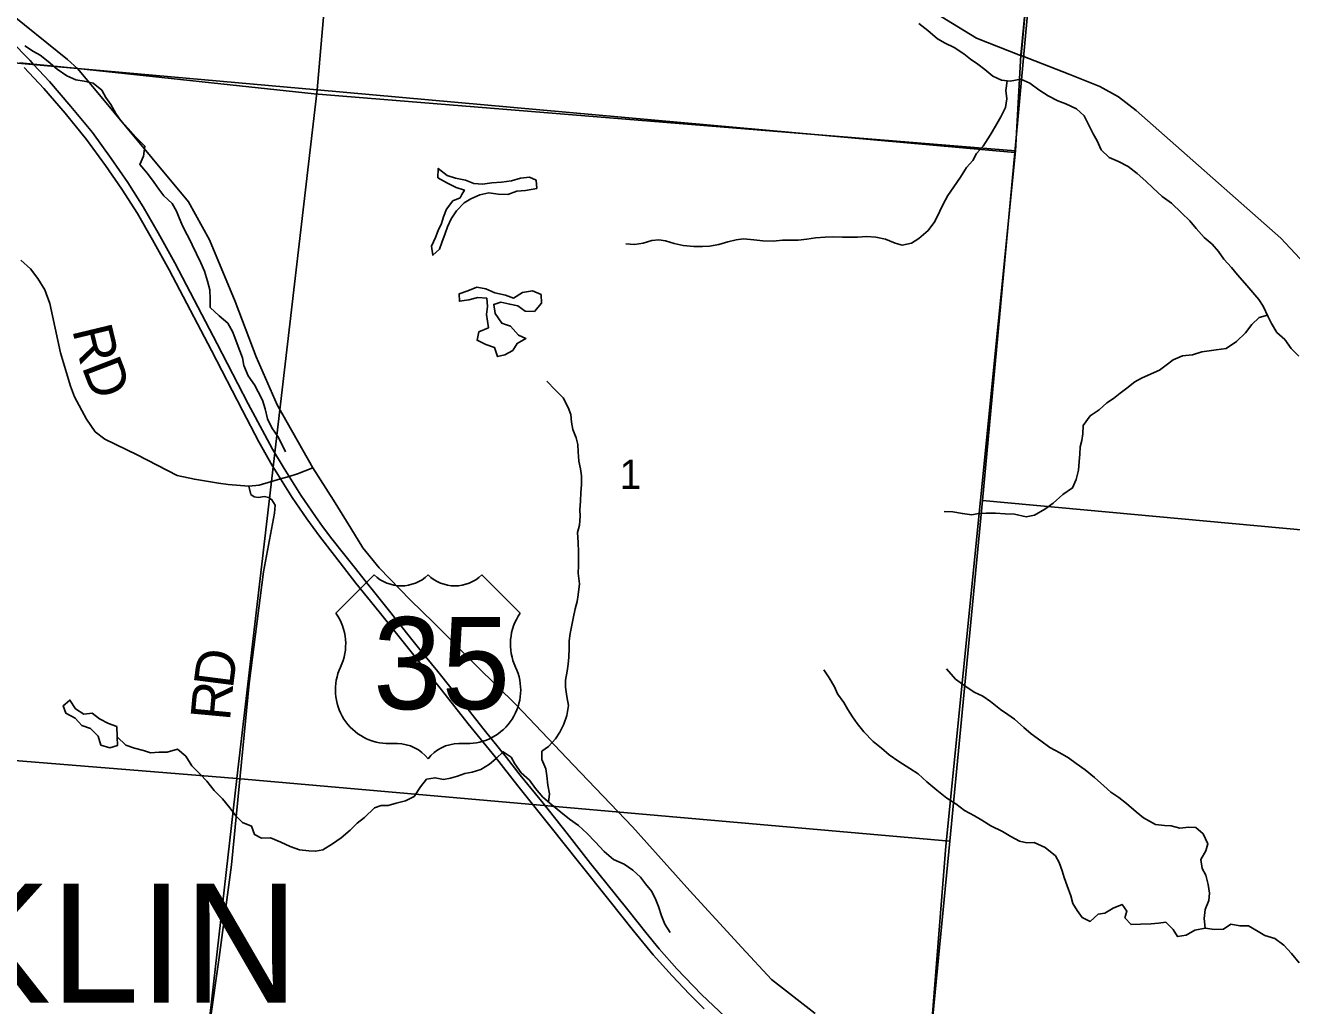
# Model space of a CAD drawing. Extents: x 0 to 42, y 0 to 22.
# Drawn here: x 4.613 to 5.519, y 18.932 to 19.634 of the extents above; entities that cross this region are included whole.
import ezdxf

# ---------------------------------------------------------------- set-up
doc = ezdxf.new("R2010")
doc.units = 0
for name, color, linetype in [('GM_X_County_Road', 7, 'Continuous'), ('GM_X_County_Road_Text', 7, 'Continuous'), ('GM_X_Minor_Lake', 7, 'Continuous'), ('GM_X_Minor_River', 7, 'Continuous'), ('GM_X_Section', 7, 'Continuous'), ('GM_X_Section_Text', 7, 'Continuous'), ('GM_X_Township', 7, 'Continuous'), ('GM_X_Township_Road', 7, 'Continuous'), ('GM_X_Township_Road_Text', 7, 'Continuous'), ('GM_X_Township_Text', 7, 'Continuous'), ('GM_X_US_Location', 7, 'Continuous'), ('GM_X_US_Route', 7, 'Continuous'), ('GM_X_US_Shield', 7, 'Continuous')]:
    doc.layers.add(name, color=color, linetype=linetype)

msp = doc.modelspace()

# ---------------------------------------------------------------- linework, layer by layer
at = {"layer": 'GM_X_County_Road'}
for points in [[(4.56999, 19.90283), (4.62719, 19.905), (4.65123, 19.90408), (4.71319, 19.89287), (4.78901, 19.87893), (4.84181, 19.86545), (4.89019, 19.84005), (4.95082, 19.79872), (4.99136, 19.77157), (5.00597, 19.76108), (5.01352, 19.75892), (5.02324, 19.75676), (5.04483, 19.75461), (5.06318, 19.75461), (5.07721, 19.75137), (5.09016, 19.74814), (5.10635, 19.74058), (5.13071, 19.7321), (5.18067, 19.69826), (5.21435, 19.67373), (5.29367, 19.62493), (5.32517, 19.61272)], [(4.59734, 19.64654), (4.64306, 19.60986), (4.65044, 19.60313), (4.72963, 19.50788), (4.7446, 19.48056), (4.76309, 19.43651), (4.77807, 19.39686), (4.79303, 19.3625), (4.81848, 19.31743), (4.83337, 19.29427), (4.84568, 19.27418), (4.85426, 19.26009), (4.86608, 19.24568), (4.88842, 19.22268), (4.90493, 19.20649), (4.93634, 19.17507), (4.96415, 19.14754), (5.00529, 19.10436), (5.04743, 19.06016), (5.08856, 19.01444), (5.12563, 18.9738), (5.14696, 18.95094), (5.17825, 18.92667)], [(5.32517, 19.61272), (5.32564, 19.61254), (5.36052, 19.59906), (5.38208, 19.59043), (5.39538, 19.58306), (5.40796, 19.57318), (5.51147, 19.48189), (5.55598, 19.43435), (5.59644, 19.39927), (5.61778, 19.3761), (5.63493, 19.35748), (5.63974, 19.35428), (5.64703, 19.35096), (5.6616, 19.345), (5.67378, 19.34602), (5.70224, 19.33874), (5.7982, 19.31027), (5.82798, 19.30233), (5.84783, 19.30034), (5.90342, 19.3063), (5.99019, 19.31629), (6.04688, 19.31444), (6.10243, 19.31289)], [(4.60949, 19.46598), (4.61651, 19.45974), (4.62181, 19.45303), (4.6268, 19.44492), (4.63024, 19.4351), (4.638, 19.39961), (4.64505, 19.37587), (4.64787, 19.36811), (4.65656, 19.35213), (4.66267, 19.34319), (4.66972, 19.33779), (4.69274, 19.32674), (4.72141, 19.31193), (4.73386, 19.30911), (4.75114, 19.30642)], [(4.75114, 19.30642), (4.75806, 19.30535), (4.77267, 19.30415), (4.78027, 19.30496), (4.79547, 19.30952), (4.80158, 19.31124), (4.80769, 19.31296), (4.81848, 19.31743)]]:
    msp.add_lwpolyline(points, dxfattribs=at)
at = {"layer": 'GM_X_Minor_Lake'}
for points in [[(4.97888, 19.51727), (4.97853, 19.52333), (4.97361, 19.52544), (4.96718, 19.52489), (4.96074, 19.52282), (4.95373, 19.5219), (4.94673, 19.52135), (4.94011, 19.52042), (4.93387, 19.52101), (4.92782, 19.52331), (4.92063, 19.52485), (4.91478, 19.52676), (4.90836, 19.53171), (4.90815, 19.52508), (4.91495, 19.52126), (4.92118, 19.51821), (4.92704, 19.51629), (4.92529, 19.51314)], [(4.92529, 19.51314), (4.92399, 19.5108), (4.91888, 19.50855), (4.91431, 19.50268), (4.91203, 19.49719), (4.91068, 19.49227), (4.90821, 19.48734), (4.9063, 19.48223), (4.90344, 19.47598), (4.90455, 19.46953), (4.9093, 19.47388), (4.91083, 19.4788), (4.91331, 19.48505), (4.91503, 19.48998), (4.91751, 19.49566), (4.92131, 19.50133), (4.92701, 19.507), (4.93175, 19.51002), (4.93819, 19.51284), (4.94463, 19.51434), (4.95125, 19.51337), (4.95806, 19.51297), (4.96469, 19.51541), (4.97093, 19.51596), (4.97888, 19.51727)], [(4.9564, 19.42008), (4.95377, 19.42102), (4.94906, 19.42786), (4.94814, 19.43431), (4.95306, 19.436), (4.95949, 19.43447), (4.96535, 19.43331), (4.97064, 19.4295), (4.97726, 19.42929), (4.9822, 19.43534), (4.98203, 19.44141), (4.9758, 19.44408), (4.96879, 19.44278), (4.96234, 19.43882), (4.95649, 19.44092), (4.94892, 19.44265), (4.94231, 19.44552), (4.93607, 19.44668), (4.92963, 19.44404), (4.92338, 19.44198), (4.92355, 19.43667), (4.93017, 19.43759), (4.93661, 19.43928), (4.94304, 19.43888), (4.94359, 19.43281), (4.94301, 19.42712), (4.9443, 19.41764)], [(4.9443, 19.41764), (4.93748, 19.41482), (4.93613, 19.40875), (4.94236, 19.4057), (4.9486, 19.40359), (4.95085, 19.39695), (4.95596, 19.39826), (4.96184, 19.40146), (4.96488, 19.40639), (4.97114, 19.40997), (4.96585, 19.41245), (4.96019, 19.41873), (4.9564, 19.42008)], [(4.64134, 19.1482), (4.63987, 19.14691), (4.64175, 19.1416), (4.64855, 19.13797), (4.65326, 19.13284), (4.6595, 19.13073), (4.66496, 19.12521), (4.66683, 19.11876), (4.67326, 19.11684), (4.67876, 19.11853), (4.67859, 19.12479)], [(4.67859, 19.12479), (4.67823, 19.132), (4.67238, 19.13429), (4.66576, 19.13754), (4.66067, 19.14173), (4.65461, 19.14099), (4.64857, 19.1448), (4.64462, 19.15107), (4.64134, 19.1482)]]:
    msp.add_lwpolyline(points, dxfattribs=at)
at = {"layer": 'GM_X_Minor_River'}
for points in [[(5.52433, 19.39739), (5.51887, 19.40291), (5.51435, 19.40918), (5.50869, 19.41432), (5.50492, 19.42078), (5.50248, 19.42553), (5.49891, 19.43312), (5.4959, 19.43787), (5.49157, 19.443), (5.48572, 19.44966), (5.48063, 19.45555), (5.4763, 19.46088), (5.47064, 19.46677), (5.46688, 19.47229), (5.46236, 19.47742), (5.4567, 19.48237), (5.45104, 19.48883), (5.44652, 19.49416), (5.44048, 19.50005), (5.43332, 19.5069), (5.42671, 19.51167), (5.41992, 19.51794), (5.41483, 19.5227), (5.40879, 19.52803), (5.40238, 19.53317), (5.39539, 19.5368), (5.38878, 19.53947), (5.38293, 19.54499), (5.38011, 19.55144), (5.3771, 19.55657), (5.37071, 19.56949), (5.36525, 19.57444), (5.35769, 19.57806), (5.35202, 19.58017), (5.34503, 19.58379), (5.33842, 19.58798), (5.33182, 19.59274), (5.32539, 19.59561), (5.31782, 19.59431), (5.31158, 19.5949), (5.30535, 19.59776), (5.29969, 19.60252), (5.29459, 19.60633), (5.2895, 19.60994), (5.28459, 19.61375), (5.27779, 19.61833), (5.27137, 19.62138), (5.26571, 19.62462), (5.25891, 19.63052), (5.25231, 19.63547)], [(4.61235, 19.61953), (4.61858, 19.61553), (4.62349, 19.61286), (4.62915, 19.60829), (4.63557, 19.60277), (4.64255, 19.598), (4.64897, 19.59514), (4.65484, 19.59417), (4.66127, 19.59282), (4.66749, 19.58768), (4.6705, 19.58255), (4.67389, 19.57761), (4.67746, 19.57115), (4.68085, 19.5664), (4.68632, 19.56031), (4.69179, 19.55404), (4.6982, 19.54776), (4.69742, 19.54056), (4.69475, 19.5345), (4.70021, 19.52822), (4.70492, 19.52157), (4.70831, 19.51682), (4.71189, 19.51207), (4.71793, 19.50674), (4.72094, 19.50123), (4.723, 19.49648), (4.72488, 19.49173)], [(5.31557, 19.59452), (5.31458, 19.58749), (5.31551, 19.58161), (5.31435, 19.57536), (5.31111, 19.56873), (5.3073, 19.56192), (5.3035, 19.55548), (5.29836, 19.54773), (5.2938, 19.54243), (5.29095, 19.53732), (5.28658, 19.5324), (5.2822, 19.52559), (5.27745, 19.51859), (5.27308, 19.51235), (5.26984, 19.5061), (5.26755, 19.50118), (5.26374, 19.4938), (5.25899, 19.48718), (5.25235, 19.48151), (5.24704, 19.4783), (5.24041, 19.47681), (5.2355, 19.47815), (5.22851, 19.48102), (5.22151, 19.48255), (5.21508, 19.48295), (5.20846, 19.48241), (5.20297, 19.48242), (5.19767, 19.48263), (5.19105, 19.48265), (5.18537, 19.48248), (5.17837, 19.48193), (5.17231, 19.48119), (5.16607, 19.48045), (5.15982, 19.48047), (5.1549, 19.4803), (5.14809, 19.47975), (5.14071, 19.47978), (5.13428, 19.48055), (5.12691, 19.48134), (5.1216, 19.4806), (5.11573, 19.4791), (5.10911, 19.47722), (5.10248, 19.47611), (5.09756, 19.47593), (5.09132, 19.47576), (5.08375, 19.47654), (5.07732, 19.47808), (5.07109, 19.47981), (5.06617, 19.48058), (5.06125, 19.48022), (5.055, 19.47815), (5.04875, 19.47722), (5.0427, 19.47781)], [(4.72488, 19.49173), (4.72713, 19.4868), (4.72995, 19.48167), (4.7322, 19.47692), (4.73521, 19.47065), (4.73841, 19.4642), (4.74103, 19.45812), (4.74328, 19.4511), (4.74477, 19.44483), (4.74513, 19.4382), (4.74511, 19.43213), (4.75152, 19.42623), (4.75775, 19.4209), (4.76132, 19.41444), (4.76376, 19.40798), (4.76638, 19.40115), (4.76826, 19.39602), (4.76918, 19.39052), (4.77219, 19.38331), (4.77671, 19.37666), (4.77934, 19.37172), (4.78254, 19.36583), (4.78441, 19.35957), (4.78608, 19.35235), (4.78928, 19.34609), (4.79342, 19.33982), (4.79605, 19.33488), (4.79906, 19.3288)], [(5.50195, 19.42665), (5.49605, 19.42498), (5.49073, 19.42007), (5.48617, 19.41401), (5.4799, 19.40778), (5.47251, 19.40287), (5.46531, 19.40176), (5.4602, 19.4012), (5.4549, 19.40046), (5.44827, 19.39821), (5.44127, 19.39747), (5.43445, 19.39465), (5.42951, 19.39087), (5.42477, 19.38729), (5.41871, 19.38465), (5.4117, 19.38164), (5.40696, 19.379), (5.40126, 19.37428), (5.39652, 19.37088), (5.39178, 19.36692), (5.38704, 19.3639), (5.38153, 19.35899), (5.37509, 19.35446), (5.36995, 19.34765), (5.36993, 19.34177), (5.36916, 19.33703), (5.36801, 19.33229), (5.36761, 19.32718), (5.36721, 19.32187), (5.36662, 19.31561), (5.36509, 19.30898), (5.36242, 19.30292), (5.35559, 19.2982), (5.34857, 19.29197), (5.3425, 19.28763), (5.3353, 19.28348), (5.32924, 19.28236), (5.32092, 19.28409), (5.3143, 19.2843), (5.3073, 19.2849), (5.30068, 19.28492), (5.29519, 19.28456), (5.29027, 19.28362), (5.28365, 19.28459), (5.27684, 19.28575), (5.2706, 19.28596)], [(4.9874, 19.07795), (4.988, 19.08378), (4.98688, 19.09004), (4.98615, 19.09668), (4.98541, 19.1018), (4.98259, 19.10844), (4.98261, 19.11432), (4.98735, 19.11772), (4.99229, 19.1232), (4.99534, 19.12812), (4.99819, 19.1338), (5.00049, 19.14005), (5.00165, 19.14706), (5.00053, 19.15351), (4.99942, 19.16034), (4.99944, 19.16527), (5.00059, 19.17172), (5.00137, 19.17664), (5.00176, 19.18176), (5.00216, 19.18821), (5.00218, 19.19333), (5.00277, 19.19864), (5.00392, 19.2047), (5.00489, 19.20944), (5.00642, 19.21626), (5.00777, 19.22156), (5.00854, 19.22649), (5.00951, 19.23426), (5.00859, 19.24185), (5.0088, 19.24716), (5.00882, 19.25209), (5.00883, 19.25721), (5.00848, 19.26385), (5.00812, 19.27105), (5.00947, 19.27617), (5.01006, 19.28261), (5.00969, 19.28735), (5.01009, 19.29342), (5.01049, 19.29968), (5.01089, 19.30517), (5.01091, 19.31162), (5.01017, 19.31674), (5.00906, 19.32206), (5.00851, 19.32888), (5.00834, 19.334), (5.00703, 19.33875), (5.00478, 19.34482), (5.00385, 19.34995), (5.00331, 19.35564), (5.00143, 19.36057), (4.99767, 19.36741), (4.99201, 19.37331), (4.98598, 19.37939)], [(5.20482, 19.13903), (5.20162, 19.14416), (5.19861, 19.14929), (5.19428, 19.15556), (5.19202, 19.1605), (5.18826, 19.16696), (5.1845, 19.17266)], [(5.45746, 18.98767), (5.45672, 18.99449), (5.4575, 19.00094), (5.45999, 19.00757), (5.46038, 19.01269), (5.45965, 19.01895), (5.45797, 19.02559), (5.45533, 19.03034), (5.45422, 19.03679), (5.45784, 19.04303), (5.45937, 19.04815), (5.45599, 19.05517), (5.4507, 19.05974), (5.44578, 19.05995), (5.43935, 19.0594), (5.43311, 19.06094), (5.42819, 19.06114), (5.42195, 19.06192), (5.41326, 19.06669), (5.40798, 19.07107), (5.40119, 19.07697), (5.39553, 19.08116), (5.38986, 19.08516), (5.38496, 19.08953), (5.37817, 19.09562), (5.37157, 19.10096), (5.36515, 19.10553), (5.35948, 19.10972), (5.35325, 19.11334), (5.34627, 19.11715), (5.33966, 19.12191), (5.33287, 19.12687), (5.32758, 19.13143), (5.32098, 19.13733), (5.31607, 19.14076), (5.31098, 19.14438), (5.30362, 19.1499), (5.29833, 19.15371), (5.2921, 19.15677), (5.2853, 19.16134), (5.2787, 19.16591), (5.2721, 19.17333)], [(5.52473, 18.9628), (5.51927, 18.96945), (5.5138, 18.97554), (5.5072, 18.9803), (5.5002, 18.98241), (5.49529, 18.98527), (5.4885, 18.98946), (5.48225, 18.98929), (5.47582, 18.99045), (5.47051, 18.98686), (5.46408, 18.9867), (5.45746, 18.98767), (5.45007, 18.98617), (5.44382, 18.98278), (5.43757, 18.98166), (5.43456, 18.98679), (5.42928, 18.99193), (5.42398, 18.99119), (5.41868, 18.99083), (5.41111, 18.99047), (5.4043, 18.9903), (5.39996, 18.99506), (5.4013, 18.99979), (5.39791, 19.00474), (5.39147, 19.0021), (5.38559, 18.99852), (5.38067, 18.99759), (5.37498, 18.99248), (5.36931, 18.99535), (5.36573, 19.00029), (5.36272, 19.00523), (5.36123, 19.01092), (5.3586, 19.01795), (5.35654, 19.02402), (5.35505, 19.02876), (5.35298, 19.03465), (5.35016, 19.0394), (5.3428, 19.04549), (5.33487, 19.04893), (5.32976, 19.04876), (5.32447, 19.0501), (5.31823, 19.05334), (5.31219, 19.05697), (5.30388, 19.06097), (5.29746, 19.06498), (5.29236, 19.06822), (5.285, 19.07203), (5.27896, 19.07679), (5.27235, 19.08079), (5.26537, 19.0865), (5.2582, 19.09259), (5.25198, 19.09811), (5.24594, 19.10211), (5.2382, 19.10707), (5.23121, 19.11183), (5.22574, 19.11659), (5.2197, 19.12135), (5.2131, 19.1282), (5.20821, 19.13428), (5.20482, 19.13903)], [(5.07431, 18.98452), (5.07055, 18.9906), (5.0683, 18.99649), (5.06605, 19.00313), (5.06417, 19.00788), (5.06117, 19.01396), (5.05683, 19.01947), (5.05325, 19.02422), (5.04778, 19.02917), (5.04137, 19.03355), (5.03381, 19.0368), (5.02702, 19.04269), (5.0208, 19.04954), (5.01495, 19.05544), (5.00873, 19.06115), (5.00231, 19.06572), (4.99609, 19.07067), (4.98967, 19.076), (4.98326, 19.08151), (4.97798, 19.08779), (4.97365, 19.09368), (4.9678, 19.09882), (4.96309, 19.10528), (4.96046, 19.11003), (4.9548, 19.11403), (4.94986, 19.10912), (4.94512, 19.10515), (4.93886, 19.10119), (4.93261, 19.0995), (4.9275, 19.09838), (4.9222, 19.0965), (4.91708, 19.095), (4.91216, 19.09426), (4.90611, 19.09541), (4.90005, 19.0943), (4.89568, 19.08881), (4.89112, 19.082), (4.88486, 19.0788), (4.87823, 19.07711), (4.87255, 19.07561), (4.86744, 19.07544), (4.86271, 19.07375), (4.85568, 19.06694), (4.85037, 19.06279), (4.84525, 19.05788), (4.83879, 19.0524), (4.83254, 19.04806), (4.82571, 19.04372), (4.8206, 19.04279), (4.81568, 19.04318), (4.80906, 19.04377), (4.80244, 19.04607), (4.79564, 19.04932), (4.78827, 19.05237), (4.78184, 19.05221), (4.77674, 19.05469), (4.77468, 19.06076), (4.76825, 19.06325), (4.76354, 19.06819), (4.75921, 19.0739), (4.75393, 19.08036), (4.7479, 19.08626), (4.74262, 19.09291), (4.73791, 19.09786), (4.73207, 19.10394), (4.72755, 19.11079), (4.7217, 19.11592), (4.71431, 19.11367), (4.70864, 19.11369), (4.70239, 19.11333), (4.69729, 19.11487), (4.69086, 19.1166), (4.68481, 19.1187), (4.67859, 19.12479)]]:
    msp.add_lwpolyline(points, dxfattribs=at)
at = {"layer": 'GM_X_Section'}
for points in [[(4.36789, 20.12963), (4.86433, 20.0791), (4.82175, 19.58796), (4.32304, 19.63244)], [(5.36588, 20.02875), (5.34375, 19.79124), (5.32103, 19.54312), (4.82175, 19.58796), (4.86433, 20.0791)], [(5.34375, 19.79124), (5.96521, 19.74271), (5.92489, 19.23623), (5.29794, 19.29404), (5.32103, 19.54312)], [(4.30012, 19.63416), (4.32304, 19.63244), (4.82175, 19.58796), (4.76421, 19.09495), (4.24825, 19.13659)], [(5.32103, 19.54312), (5.29794, 19.29404), (5.27466, 19.05009), (4.76421, 19.09495), (4.82175, 19.58796)], [(5.29794, 19.29404), (5.92489, 19.23623), (5.88694, 18.72342), (5.24862, 18.78217), (5.27466, 19.05009)], [(4.76421, 19.09495), (4.70656, 18.58779), (4.20614, 18.62998), (4.24825, 19.13659)], [(4.76421, 19.09495), (5.27466, 19.05009), (5.24862, 18.78217), (5.22327, 18.54106), (4.70656, 18.58779)]]:
    msp.add_lwpolyline(points, close=True, dxfattribs=at)
at = {"layer": 'GM_X_Township'}
msp.add_lwpolyline([(5.14624, 17.76794), (5.1674, 18.00102), (5.17029, 18.01018), (5.19596, 18.27109), (5.23598, 18.67597), (5.24802, 18.79207), (5.25291, 18.82566), (5.25334, 18.82864), (5.25368, 18.83198), (5.25833, 18.87833), (5.2718, 19.04643), (5.3216, 19.54433), (5.32553, 19.6128), (5.332, 19.68245), (5.33749, 19.74156), (5.35499, 19.92984), (5.38817, 20.287), (5.7544, 20.26066), (6.25694, 20.21504), (6.30624, 20.21096), (6.44864, 20.19642)], dxfattribs=at)
at = {"layer": 'GM_X_Township_Road'}
for points in [[(4.60887, 19.60735), (4.61368, 19.60698), (4.61855, 19.6065), (4.65033, 19.6034), (4.81946, 19.58526), (5.3216, 19.54433), (5.32553, 19.6128), (5.332, 19.68245), (5.33749, 19.74156), (5.35499, 19.92984), (5.38817, 20.287), (5.40834, 20.52112), (5.42813, 20.71602), (5.42978, 20.72026), (5.43118, 20.73056), (5.43171, 20.7371), (5.4327, 20.74917), (5.44663, 20.9), (2.33491, 20.9)], [(5.33211, 19.68219), (5.32564, 19.61254)], [(5.14624, 17.76794), (5.1674, 18.00102), (5.17029, 18.01018), (5.19596, 18.27109), (5.23598, 18.67597), (5.24802, 18.79207), (5.25291, 18.82566), (5.25334, 18.82864), (5.25368, 18.83198), (5.25833, 18.87833), (5.2718, 19.04643), (5.3216, 19.54433), (4.81946, 19.58526), (4.65033, 19.6034), (4.61855, 19.6065), (4.61368, 19.60698), (4.60887, 19.60735)], [(4.72096, 18.68899), (4.73139, 18.82557), (4.75154, 18.9667), (4.76043, 19.03311), (4.77288, 19.16297), (4.78319, 19.24293), (4.79112, 19.28487), (4.79161, 19.2907), (4.78934, 19.29443), (4.78708, 19.29621), (4.78384, 19.2967), (4.77963, 19.29621), (4.77655, 19.29653), (4.77412, 19.29832), (4.77267, 19.30415)]]:
    msp.add_lwpolyline(points, dxfattribs=at)
at = {"layer": 'GM_X_US_Route'}
for points in [[(4.60187, 19.62351), (4.61614, 19.60894), (4.61866, 19.60624), (4.63009, 19.59405), (4.64545, 19.57621), (4.66078, 19.55743), (4.67422, 19.53891), (4.68608, 19.52178), (4.69717, 19.50433), (4.70795, 19.48564), (4.71989, 19.46408), (4.75013, 19.40623), (4.77231, 19.36328), (4.7841, 19.34094), (4.7896, 19.33081), (4.79794, 19.31684), (4.80158, 19.31124)], [(4.61201, 19.60399), (4.62597, 19.5891), (4.64132, 19.57126), (4.65666, 19.55248), (4.67009, 19.53396), (4.68195, 19.51683), (4.69304, 19.49938), (4.70382, 19.48069), (4.71576, 19.45913), (4.74601, 19.40129), (4.76818, 19.35833), (4.77997, 19.33599), (4.78943, 19.31909), (4.79276, 19.31371), (4.79547, 19.30952)], [(4.80158, 19.31124), (4.80989, 19.29775), (4.8205, 19.28245), (4.82555, 19.27529), (4.83229, 19.26649), (4.83961, 19.2572), (4.84916, 19.24527), (4.85615, 19.23631), (4.86306, 19.22775), (4.87441, 19.21353), (4.88564, 19.19922), (4.89897, 19.18252), (4.90796, 19.1715), (4.91734, 19.15974), (4.92976, 19.14419), (4.94119, 19.12971), (4.95715, 19.10989), (4.96702, 19.09731), (4.98338, 19.07708), (5.00057, 19.05536), (5.01744, 19.03406), (5.03537, 19.01169), (5.04507, 18.9996), (5.05691, 18.98463), (5.06646, 18.97287), (5.07912, 18.95847), (5.09682, 18.94007), (5.11383, 18.92426)], [(4.79547, 19.30952), (4.80378, 19.29603), (4.81439, 19.28073), (4.82327, 19.26831), (4.83397, 19.25457), (4.84943, 19.23483), (4.86604, 19.21411), (4.87953, 19.19749), (4.89286, 19.1808), (4.9107, 19.15826), (4.92987, 19.13391), (4.94903, 19.11039), (4.9654, 19.0895), (4.98917, 19.05989), (5.00874, 19.0353), (5.03046, 19.00799), (5.04814, 18.98587), (5.06212, 18.96868), (5.07578, 18.95363), (5.08828, 18.9403), (5.09881, 18.92994)]]:
    msp.add_lwpolyline(points, dxfattribs=at)
at = {"layer": 'GM_X_US_Shield'}
for p, q in [((4.8626, 19.24066), (4.83514, 19.2132)), ((4.96697, 19.2132), (4.93951, 19.24066)), ((4.87359, 19.11981), (4.87908, 19.11981)), ((4.92303, 19.11981), (4.92852, 19.11981))]:
    msp.add_line(p, q, dxfattribs=at)
for centre, radius, start, end in [((4.88183, 19.26028), 0.02747, 225.573, 314.427), ((4.92028, 19.26028), 0.02747, 225.573, 314.427), ((4.80364, 19.19114), 0.03845, 334.54712, 35.00093), ((4.99847, 19.19114), 0.03845, 144.99907, 205.45288), ((4.87316, 19.15826), 0.03845, 154.83192, 270.63826), ((4.92895, 19.15826), 0.03845, 269.36174, 25.16808), ((4.87908, 19.09235), 0.02747, 36.8699, 90), ((4.92303, 19.09235), 0.02747, 90, 143.1301)]:
    msp.add_arc(centre, radius, start, end, dxfattribs=at)

# ---------------------------------------------------------------- texts
at = {"layer": 'GM_X_County_Road_Text'}
for s, rotation, p in [('R', 283.51562, (4.64624, 19.41622)), ('D', 290.93843, (4.65286, 19.38976))]:
    msp.add_text(s, height=0.02841, rotation=rotation, dxfattribs=at).set_placement(p)
at = {"layer": 'GM_X_Section_Text'}
msp.add_text('1', height=0.02093, rotation=0.00001, dxfattribs=at).set_placement((5.03814, 19.30226))
at = {"layer": 'GM_X_Township_Road_Text'}
for s, rotation, p in [('D', 82.66894, (4.76131, 19.15863)), ('R', 84.70768, (4.75919, 19.13567))]:
    msp.add_text(s, height=0.02841, rotation=rotation, dxfattribs=at).set_placement(p)
at = {"layer": 'GM_X_Township_Text'}
msp.add_text('FRANKLIN', height=0.085227, rotation=0.00001, dxfattribs=at).set_placement((4.2447, 18.93442))
at = {"layer": 'GM_X_US_Location'}
for s, p in [('0', (4.90102, 19.17697)), ('/', (4.90103, 19.17697))]:
    msp.add_text(s, height=0.0000947, dxfattribs=at).set_placement(p)
msp.add_text('35', height=0.0000947, rotation=0.00001, dxfattribs=at).set_placement((4.88147, 19.15737))
at = {"layer": 'GM_X_US_Shield'}
msp.add_text('35', height=0.065918, dxfattribs=at).set_placement((4.86174, 19.14453))

doc.saveas('drawing.dxf')
